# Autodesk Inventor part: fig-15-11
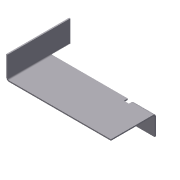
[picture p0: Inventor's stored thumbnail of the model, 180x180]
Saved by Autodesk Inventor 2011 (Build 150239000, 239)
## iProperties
Shininess: 77.0
Angle Display Precision: 2
Document Length Units: 11269
Document Angle Units: 11279
Document Time Units: 11290
Document Mass Units: 11283
Document Length Units Precision: 3
Document Angle Units Precision: 2
Created: 2002-04
Part Number: fig-15-11
Material: Aluminum-6061
Document SubType Name: Sheet Metal
Density: 1 g/cm^3
Sheet Metal Rule: Default
Density: 0.0
Volumn: 0.0
Area: 0.0
PropertySet Name: Model Information
Control State: 0
Master: False
Checked Out: False
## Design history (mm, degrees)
node "Face1"
  sketch "Sketch1"
    geometry: L1 (-49.559, 19.574)-(-49.559, -30.426); L2 (-49.559, -30.426)-(50.441, -30.426); L3 (50.441, -30.426)-(50.441, 19.574); L4 (50.441, 19.574)-(32.941, 19.574); L5 (32.941, 19.574)-(32.941, 4.574); L6 (32.941, 4.574)-(-32.059, 4.574); L7 (-32.059, 4.574)-(-32.059, 19.574); L8 (-32.059, 19.574)-(-49.559, 19.574)
    constraints: 16 end point, 6 parallel, 2 equal length, 1 perpendicular, 1 vertical
    dimensions: "d0" = 100 distance of L1.end L2.end; "d1" = 65 distance of L5.end L6.end; "d2" = 15 distance of L6.end L7.end; "d3" = 50 distance of L1.start L1.end
sketch "Sketch2"
  geometry: L1 (100, 0)-(0, 0) reference; L2 (17.5, 50)-(17.5, 35) reference; L3 (82.5, 50)-(82.5, 0)
  constraints: 2 end point, 1 parallel, 1 point on line
sketch "Sketch3"
  geometry: L1 (81.369, -50)-(0, -50) reference; L2 (17.5, 0)-(17.5, -50)
  constraints: 2 end point, 1 perpendicular, 1 point on line
feature "Fold2" sketch "Sketch3" dims "d8" = 1 (= BendRadius), "d9" = 90 deg, "d10" = 1 (= BendRadius), "d14" = 1 (= BendReliefWidth), "d15" = 0.5 (= BendReliefDepth), "d16" = 2 (= MinimumRemnant), "SeamGap" = 0.01, "Thickness" = 1
sketch "Sketch4"
  geometry: L1 (17.5, 0)-(17.5, -50) reference; L2 (-63.869, -15)-(0, -15) reference; L3 (0, -15)-(17.5, -15)
  constraints: 2 end point, 1 collinear, 1 point on line
feature "Fold3" sketch "Sketch4" dims "d11" = 1 (= BendRadius), "d12" = 90 deg, "d13" = 1 (= BendRadius), "d17" = 4, "d18" = 2, "d19" = 2 (= MinimumRemnant), "SeamGap" = 0.01, "Thickness" = 1
body "Solid1"
face "Plate1" dims "Thickness" = 1
other parameters: "BendRadius" = 1 (= Thickness), "BendReliefWidth" = 1 (= Thickness), "BendReliefDepth" = 0.5 (= 0.5 x Thickness), "CornerReliefSize" = 4 (= 4 x Thickness), "MinimumRemnant" = 2 (= 2 x Thickness), "TransitionRadius" = 1 (= BendRadius), "d4" = 1 (= BendRadius), "JacobiRadiusSize" = 1 (= Thickness), "GapSize" = 1 (= Thickness)
